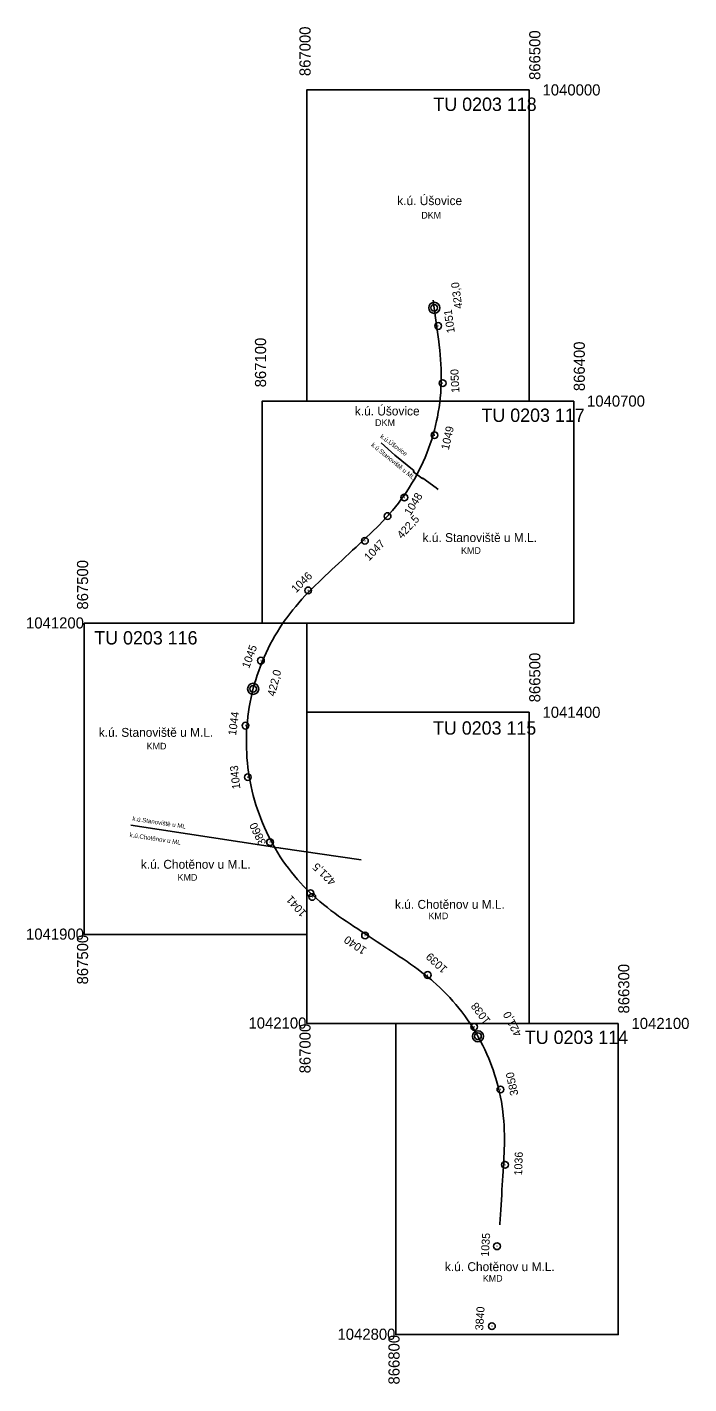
# Model space of a CAD drawing. Extents: x -867628 to -843257, y -1065611 to -1039859.
# Drawn here: x -867628 to -866141, y -1042911 to -1039859 of the extents above; entities that cross this region are included whole.
import ezdxf

# ---------------------------------------------------------------- set-up
doc = ezdxf.new("R2010")
doc.units = 0
for name, color, linetype in [('Vrstva 1', 7, 'Continuous'), ('Vrstva 10', 7, 'Continuous'), ('Vrstva 55', 7, 'Continuous'), ('Vrstva 62', 7, 'Continuous'), ('Vrstva 63', 7, 'Continuous'), ('Vrstva 7', 7, 'Continuous')]:
    doc.layers.add(name, color=color, linetype=linetype)

msp = doc.modelspace()

# ---------------------------------------------------------------- linework, layer by layer
at = {"layer": 'Vrstva 1'}
for points in [[(-866714.8, -1040480.5), (-866715.1, -1040478.6), (-866715.8, -1040473.2)], [(-866708.1, -1040744.4), (-866706.5, -1040736.3), (-866704.4, -1040724.9), (-866702.6, -1040714.2), (-866701.2, -1040703.4), (-866700, -1040692.6), (-866699, -1040681.8), (-866698.3, -1040670.9), (-866697.9, -1040660), (-866697.7, -1040649.2), (-866697.7, -1040638.2), (-866698, -1040627.5), (-866698.5, -1040617.3), (-866699.2, -1040606.8), (-866700.1, -1040596), (-866701.1, -1040585.3), (-866702.4, -1040574.2), (-866703.3, -1040566.4), (-866704.6, -1040555.8), (-866706, -1040545.2), (-866707.5, -1040534.3), (-866709, -1040523.3), (-866710.5, -1040512.6), (-866711.9, -1040501.8), (-866713.4, -1040491), (-866714.8, -1040480.5)], [(-866842.8, -1040984.3), (-866837.4, -1040978.9), (-866829.5, -1040970.7), (-866822, -1040962.7), (-866816.4, -1040956.5), (-866814.8, -1040954.7), (-866807.6, -1040946.4), (-866800.8, -1040938.1), (-866794, -1040929.6), (-866787.5, -1040920.8), (-866781.2, -1040912.1), (-866775.1, -1040903.1), (-866769.2, -1040894), (-866763.6, -1040884.8), (-866758.1, -1040875.4), (-866752.9, -1040866), (-866747.8, -1040856.3), (-866743, -1040846.5), (-866738.5, -1040836.8), (-866734.2, -1040826.9), (-866730.2, -1040816.9), (-866726.2, -1040806.7), (-866722.6, -1040796.5), (-866719.2, -1040786.2), (-866716.1, -1040776), (-866713.2, -1040765.5), (-866710.6, -1040755.1), (-866708.1, -1040744.4)], [(-867048.2, -1041192), (-867045.1, -1041187.7), (-867038.2, -1041178.5), (-867031.6, -1041170), (-867024.8, -1041161.8), (-867017.8, -1041153.6), (-867010.7, -1041145.5), (-867003.4, -1041137.7), (-866995.9, -1041129.8), (-866988.5, -1041122.3), (-866980.8, -1041114.6), (-866973.2, -1041107.2), (-866965.7, -1041100), (-866958.5, -1041093.2), (-866951, -1041086.2), (-866943.3, -1041079), (-866936.1, -1041072.2), (-866928.5, -1041065.1), (-866920.6, -1041057.8), (-866912.7, -1041050.4), (-866904.8, -1041043.1), (-866896.9, -1041035.7), (-866889.2, -1041028.5), (-866881.2, -1041021), (-866873.3, -1041013.6), (-866865.5, -1041006.3), (-866857.7, -1040998.9), (-866850, -1040991.4), (-866842.8, -1040984.3)], [(-867135.4, -1041448.8), (-867135.1, -1041442.5), (-867134.4, -1041431.2), (-867133.4, -1041420.5), (-867132.3, -1041409.6), (-867130.8, -1041398.9), (-867129.2, -1041388.3), (-867127.3, -1041377.7), (-867125.1, -1041367.1), (-867122.8, -1041356.6), (-867120.1, -1041345.9), (-867117.2, -1041335.5), (-867114.6, -1041326.8), (-867111.3, -1041316.5), (-867107.9, -1041306.5), (-867104.2, -1041296.5), (-867100.1, -1041286.4), (-867095.9, -1041276.4), (-867091.5, -1041266.5), (-867086.8, -1041256.8), (-867081.9, -1041247.2), (-867076.8, -1041237.7), (-867071.5, -1041228.3), (-867066, -1041219), (-867060.2, -1041209.8), (-867054.2, -1041200.7), (-867048.2, -1041192)], [(-867070.4, -1041707.1), (-867075.5, -1041698.2), (-867081, -1041688.1), (-867085.9, -1041678.5), (-867090.6, -1041668.8), (-867095.1, -1041659), (-867099.4, -1041649), (-867103.4, -1041639), (-867107.2, -1041628.8), (-867110.7, -1041618.8), (-867114.1, -1041608.5), (-867117.2, -1041598.1), (-867120.1, -1041587.6), (-867122.7, -1041577.2), (-867125.1, -1041566.7), (-867127.2, -1041556.1), (-867129.1, -1041545.6), (-867130.8, -1041535), (-867132.2, -1041524.3), (-867133.4, -1041513.6), (-867134.3, -1041502.8), (-867135, -1041491.8), (-867135.5, -1041481.2), (-867135.7, -1041470.3), (-867135.7, -1041459.5), (-867135.4, -1041448.8)], [(-866859.5, -1041904.6), (-866867.5, -1041899.3), (-866876.8, -1041893.2), (-866885.4, -1041887.5), (-866894.1, -1041881.7), (-866902.6, -1041876.1), (-866911.1, -1041870.3), (-866919.8, -1041864.4), (-866928.3, -1041858.4), (-866937, -1041852.2), (-866945.6, -1041845.8), (-866953.6, -1041839.6), (-866962.2, -1041832.8), (-866970.3, -1041826.1), (-866978.2, -1041819.3), (-866985.8, -1041812.4), (-866993.1, -1041805.5), (-867000.1, -1041798.6), (-867007.4, -1041791), (-867014.1, -1041783.8), (-867020.9, -1041776.1), (-867027.8, -1041768), (-867034.6, -1041759.6), (-867041.2, -1041751), (-867047.5, -1041742.5), (-867053.5, -1041733.9), (-867059.4, -1041724.9), (-867065, -1041716.1), (-867070.4, -1041707.1)], [(-866623, -1042115.6), (-866626.7, -1042109.5), (-866632.7, -1042100.2), (-866638.6, -1042091.6), (-866644.9, -1042082.7), (-866651.6, -1042073.9), (-866658.2, -1042065.5), (-866664.8, -1042057.6), (-866671.7, -1042049.6), (-866678.8, -1042041.8), (-866685.8, -1042034.4), (-866693.3, -1042026.8), (-866700.9, -1042019.4), (-866708.6, -1042012.2), (-866716.6, -1042005.1), (-866719.9, -1042002.3), (-866724.6, -1041998.4), (-866733.1, -1041991.5), (-866741.2, -1041985.1), (-866749.5, -1041978.9), (-866758, -1041972.6), (-866766.7, -1041966.4), (-866774.6, -1041961), (-866783.5, -1041954.9), (-866792.1, -1041949.1), (-866800.8, -1041943.3), (-866809.3, -1041937.7), (-866815.8, -1041933.4), (-866824.4, -1041927.7), (-866833.2, -1041921.9), (-866841.8, -1041916.3), (-866850.6, -1041910.5), (-866859.5, -1041904.6)], [(-866556, -1042382.5), (-866555.8, -1042372.9), (-866555.7, -1042361.8), (-866555.8, -1042350.7), (-866556.1, -1042340), (-866556.5, -1042329.6), (-866557.2, -1042319), (-866558.2, -1042308.2), (-866559.4, -1042297.8), (-866560.9, -1042286.9), (-866562.6, -1042276), (-866564.6, -1042265.7), (-866566.8, -1042255.2), (-866569.2, -1042244.6), (-866571.9, -1042234.2), (-866574.8, -1042224.2), (-866577.7, -1042214.6), (-866581.2, -1042204.2), (-866583.7, -1042197.2), (-866586.9, -1042188.6), (-866590.9, -1042178.8), (-866595.1, -1042168.9), (-866599.7, -1042158.9), (-866604.3, -1042149.3), (-866609.2, -1042139.7), (-866614.4, -1042130.2), (-866619.5, -1042121.4), (-866623, -1042115.6)], [(-866566.2, -1042553.2), (-866566.1, -1042550.8), (-866565.4, -1042540.2), (-866564.7, -1042529.8), (-866564.1, -1042519.2), (-866563.3, -1042508), (-866562.6, -1042497), (-866561.9, -1042485.8), (-866561.2, -1042474.6), (-866560.5, -1042464.1), (-866559.8, -1042453.3), (-866559.2, -1042443.1), (-866558.6, -1042433.3), (-866558.4, -1042430.5), (-866557.9, -1042422.5), (-866557.3, -1042411.9), (-866556.8, -1042401.2), (-866556.3, -1042390.9), (-866556, -1042382.5)]]:
    msp.add_lwpolyline(points, dxfattribs=at)
at = {"layer": 'Vrstva 55'}
for points in [[(-866832.4, -1040793.7), (-866802.1, -1040821.8), (-866758.8, -1040857.3)], [(-866758.8, -1040857.3), (-866760.1, -1040859.3), (-866759.8, -1040859.6), (-866754.1, -1040863.8), (-866750, -1040866.4), (-866741.6, -1040873.2), (-866740.4, -1040874.3), (-866739.4, -1040873.1), (-866709.2, -1040895.5), (-866704.7, -1040899)], [(-867395.1, -1041653.9), (-867086.6, -1041701.2)], [(-867086.6, -1041701.2), (-867069.6, -1041704), (-867062.5, -1041705.2), (-867058.6, -1041705.9), (-866877.8, -1041731.8)]]:
    msp.add_lwpolyline(points, dxfattribs=at)
at = {"layer": 'Vrstva 62'}
for points in [[(-866500, -1040000), (-866500, -1040700), (-867000, -1040700), (-867000, -1040000)], [(-866400, -1040700), (-866400, -1041200), (-867100, -1041200), (-867100, -1040700)], [(-867000, -1041200), (-867000, -1041900), (-867500, -1041900), (-867500, -1041200)], [(-866500, -1041400), (-866500, -1042100), (-867000, -1042100), (-867000, -1041400)], [(-866300, -1042100), (-866300, -1042800), (-866800, -1042800), (-866800, -1042100)]]:
    msp.add_lwpolyline(points, close=True, dxfattribs=at)
at = {"layer": 'Vrstva 63'}
for p, q in [((-866705.3, -1040531.1), (-866704.3, -1040531.1)), ((-866695, -1040659.6), (-866694, -1040659.6)), ((-866713.4, -1040776.8), (-866712.4, -1040776.8)), ((-866781.2, -1040917.1), (-866780.2, -1040917.1)), ((-866869.8, -1041014.3), (-866868.8, -1041014.3)), ((-866997.4, -1041125.9), (-866996.4, -1041125.9)), ((-867103.5, -1041283.9), (-867102.5, -1041283.9)), ((-867138.3, -1041430.2), (-867137.3, -1041430.2)), ((-867132.9, -1041545.9), (-867131.9, -1041545.9)), ((-867083, -1041692.3), (-867082, -1041692.3)), ((-866988.1, -1041815.4), (-866987.1, -1041815.4)), ((-866869.5, -1041902.1), (-866868.5, -1041902.1)), ((-866728.7, -1041991.1), (-866727.7, -1041991.1)), ((-866624.3, -1042107.9), (-866623.3, -1042107.9)), ((-866565.3, -1042248.6), (-866564.3, -1042248.6)), ((-866554.9, -1042418.1), (-866553.9, -1042418.1)), ((-866572.9, -1042601.3), (-866571.9, -1042601.3)), ((-866584.3, -1042781), (-866583.3, -1042781))]:
    msp.add_line(p, q, dxfattribs=at)
for centre in [(-866704.8, -1040531.1), (-866694.5, -1040659.6), (-866712.9, -1040776.8), (-866780.7, -1040917.1), (-866869.3, -1041014.3), (-866996.9, -1041125.9), (-867103, -1041283.9), (-867137.8, -1041430.2), (-867132.4, -1041545.9), (-867082.5, -1041692.3), (-866987.6, -1041815.4), (-866869, -1041902.1), (-866728.2, -1041991.1), (-866623.8, -1042107.9), (-866564.8, -1042248.6), (-866554.4, -1042418.1), (-866572.4, -1042601.3), (-866583.8, -1042781)]:
    msp.add_circle(centre, 7.56, dxfattribs=at)
at = {"layer": 'Vrstva 7'}
for centre, radius in [((-866713.5, -1040490.3), 12.5), ((-866713.5, -1040490.3), 7.52), ((-866818.3, -1040958.7), 7.5), ((-867120.5, -1041347.4), 12.5), ((-867120.5, -1041347.4), 7.52), ((-866991.8, -1041806.8), 7.5), ((-866615.2, -1042128.9), 12.5), ((-866615.2, -1042128.9), 7.52)]:
    msp.add_circle(centre, radius, dxfattribs=at)

# ---------------------------------------------------------------- texts
at = {"layer": 'Vrstva 10'}
for s, p in [('DKM', (-866742.6, -1040289.5)), ('DKM', (-866846.4, -1040756)), ('KMD', (-866653.2, -1041043.8)), ('KMD', (-867359.9, -1041483.7)), ('KMD', (-867290.4, -1041779)), ('KMD', (-866726.5, -1041865.5)), ('KMD', (-866604.4, -1042680.9))]:
    msp.add_text(s, height=15, dxfattribs=at).set_placement(p)
at = {"layer": 'Vrstva 55'}
for s, p in [('k.ú. Úšovice', (-866796.5, -1040259.2)), ('k.ú. Úšovice', (-866892, -1040732.4)), ('k.ú. Stanoviště u M.L.', (-866739.7, -1041017.1)), ('k.ú. Stanoviště u M.L.', (-867467.4, -1041455.3)), ('k.ú. Chotěnov u M.L.', (-867372.8, -1041752.1)), ('k.ú. Chotěnov u M.L.', (-866801.6, -1041842.2)), ('k.ú. Chotěnov u M.L.', (-866689.5, -1042657.2))]:
    msp.add_text(s, height=20, dxfattribs=at).set_placement(p)
for s, rotation, p in [('k.ú.Stanoviště u ML', 320.6991, (-866856.1, -1040800.3)), ('k.ú.Úšovice', 323.3311, (-866835.9, -1040781.7)), ('k.ú.Stanoviště u ML', 351.2805, (-867392.4, -1041643.7)), ('k.ú.Chotěnov u ML', 351.2805, (-867398.6, -1041680.5))]:
    msp.add_text(s, height=10, rotation=rotation, dxfattribs=at).set_placement(p)
at = {"layer": 'Vrstva 62'}
for s, p in [('867000', (-866991.4, -1039969.1)), ('866500', (-866475, -1039977.7)), ('867100', (-867091.4, -1040669.1)), ('866400', (-866375, -1040677.7)), ('867500', (-867491.4, -1041169.1)), ('866500', (-866475, -1041377.7)), ('867500', (-867491.4, -1042012.3)), ('866300', (-866275, -1042077.7)), ('867000', (-866991.4, -1042212.3)), ('866800', (-866791.4, -1042912.3))]:
    msp.add_text(s, height=25, rotation=90, dxfattribs=at).set_placement(p)
for s, height, p in [('1040000', 25, (-866470.1, -1040012.5)), ('TU 0203 118', 30, (-866715.3, -1040047.4)), ('1040700', 25, (-866370.1, -1040712.5)), ('TU 0203 117', 30, (-866607.3, -1040746.9)), ('1041200', 25, (-867630.9, -1041211.6)), ('TU 0203 116', 30, (-867477.5, -1041247.6)), ('1041400', 25, (-866470.1, -1041412.5)), ('TU 0203 115', 30, (-866716.2, -1041450.4)), ('1041900', 25, (-867630.9, -1041911.6)), ('1042100', 25, (-867130.9, -1042111.6)), ('1042100', 25, (-866270.1, -1042112.5)), ('TU 0203 114', 30, (-866509.8, -1042146.2)), ('1042800', 25, (-866930.9, -1042811.6))]:
    msp.add_text(s, height=height, dxfattribs=at).set_placement(p)
at = {"layer": 'Vrstva 63'}
for s, rotation, p in [('1051', 97.769, (-866667.1, -1040545.9)), ('1050', 92.7178, (-866656.8, -1040681.1)), ('1049', 77.1094, (-866680.9, -1040811)), ('1048', 58.4754, (-866766.9, -1040959)), ('1047', 45.9424, (-866860, -1041060.9)), ('1046', 44.2395, (-867024.3, -1041132.6)), ('1045', 69.6558, (-867129.7, -1041302.8)), ('1044', 82.4467, (-867159, -1041453.1)), ('1043', 96.2818, (-867149.1, -1041572.1)), ('3860', 115.8122, (-867090.4, -1041694.2)), ('1041', 131.5497, (-866998.9, -1041850.7)), ('1040', 145.9648, (-866864, -1041931.5)), ('1039', 137.1845, (-866682.5, -1041975.7)), ('1038', 126.9862, (-866585.9, -1042093.4)), ('3850', 101.8642, (-866524.4, -1042260.5)), ('1036', 88.099, (-866516.1, -1042442.4)), ('1035', 86.3444, (-866591, -1042625.3)), ('3840', 86.3574, (-866603.6, -1042790.9))]:
    msp.add_text(s, height=18, rotation=rotation, dxfattribs=at).set_placement(p)
at = {"layer": 'Vrstva 7'}
for s, rotation, p in [('423,0', 97.7569, (-866650.1, -1040491.2)), ('422,5', 47.6203, (-866786, -1041011.1)), ('422,0', 76.0076, (-867071.6, -1041365.4)), ('421,5', 136.3546, (-866933, -1041778.9)), ('421,0', 117.6064, (-866516.1, -1042124.2))]:
    msp.add_text(s, height=18, rotation=rotation, dxfattribs=at).set_placement(p)

doc.saveas('drawing.dxf')
